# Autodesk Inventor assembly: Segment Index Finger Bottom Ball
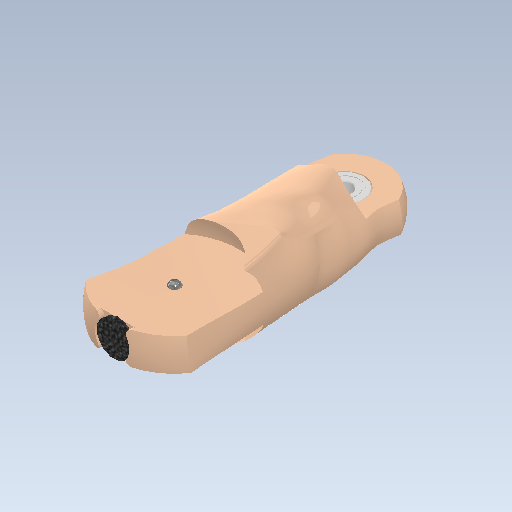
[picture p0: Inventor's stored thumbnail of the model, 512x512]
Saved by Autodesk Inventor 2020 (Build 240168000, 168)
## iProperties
Created: 2019-10
Part Number: Segment Index Finger Bottom Ball
Document SubType Name: Assembly
Designer: yello
Author: yello
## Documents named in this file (8)
- D:\1-Cours-2021-22\1STI2D\ETLV\AI\Prototype 2 (Realistic Hand)\Segment Index Finger Bottom Ball.iam
- D:\1-Cours-2021-22\1STI2D\ETLV\AI\Prototype 2 (Realistic Hand)\Segment Index Finger Bottom.ipt
- D:\1-Cours-2021-22\1STI2D\ETLV\AI\Prototype 2 (Realistic Hand)\Push Part.ipt
- D:\1-Cours-2021-22\1STI2D\ETLV\AI\Prototype 2 (Realistic Hand)\Plug.ipt
- D:\1-Cours-2021-22\1STI2D\ETLV\AI\Prototype 2 (Realistic Hand)\Spring.ipt
- D:\1-Cours-2021-22\1STI2D\ETLV\AI\Prototype 2 (Realistic Hand)\Ball.ipt
- D:\1-Cours-2021-22\1STI2D\ETLV\AI\Prototype 2 (Realistic Hand)\Lock.ipt
- D:\1-Cours-2021-22\1STI2D\ETLV\AI\Prototype 2 (Realistic Hand)\Bearings.iam
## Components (8 placed, 7 different names)
1. Segment Index Finger Bottom:1 — Mate:1, Mate:2, Mate:3, Mate:5, Mate:6, Mate:7, Mate:10, Mate:11, Flush:1
2. Push Part:1 — Mate:1, Mate:8, Mate:9
3. Plug:1 — Mate:2, Mate:3
4. Spring:1 — Mate:5
5. Ball:1 — Mate:6
6. Ball:2 — Mate:7
7. Lock:1 — Mate:8, Mate:9, Mate:10
8. Bearings:1 [sub-assembly] — Mate:11, Flush:1
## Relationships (11: Mate 10, Flush 1)
- Mate:1: Segment Index Finger Bottom:1 ↔ Push Part:1
- Mate:2: Segment Index Finger Bottom:1 ↔ Plug:1
- Mate:3: Segment Index Finger Bottom:1 ↔ Plug:1
- Mate:5: Segment Index Finger Bottom:1 ↔ Spring:1
- Mate:6: Segment Index Finger Bottom:1 ↔ Ball:1
- Mate:7: Segment Index Finger Bottom:1 ↔ Ball:2
- Mate:8: Push Part:1 ↔ Lock:1
- Mate:9: Push Part:1 ↔ Lock:1
- Mate:10: Segment Index Finger Bottom:1 ↔ Lock:1
- Mate:11: Segment Index Finger Bottom:1 ↔ Bearings:1
- Flush:1: Segment Index Finger Bottom:1 ↔ Bearings:1
